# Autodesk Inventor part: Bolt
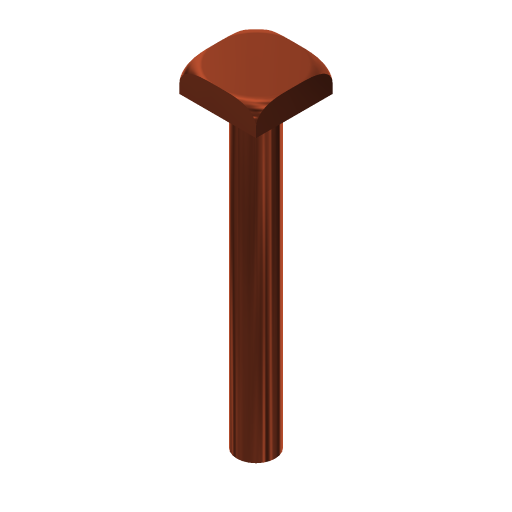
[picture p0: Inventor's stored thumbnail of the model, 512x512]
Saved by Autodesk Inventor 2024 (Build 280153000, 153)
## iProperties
Created: 2009-04
Part Number: Bolt
Document SubType Name: Modeling
Designer: Sham
Density: 8.92 g/cm^3
Material: Copper, Alloy
Appearance: Copper - Satin
Author: Sham
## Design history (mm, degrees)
sketch "Sketch1"
  geometry: L1 (-12, 12)-(12, 12); L2 (12, 12)-(12, -12); L3 (12, -12)-(-12, -12); L4 (-12, -12)-(-12, 12); 1 further point
  constraints: 8 end point, 2 parallel, 2 perpendicular, 1 horizontal, 1 other
  dimensions: "d0" = 24 distance of L1.start L1.end; "d1" = 12 distance from line of L2 point (0, 0); "d2" = 12 distance from line of L1 point (0, 0)
extrude "Extrusion1" new body sketch "Sketch1" distance "d3" = 8; taper "d4" = 0 deg
sketch "Sketch2"
  geometry: C1 r 6 at (0, 0)
  constraints: 1 centre point
  dimensions: "d5" = 12 diameter of C1
extrude "Extrusion2" join sketch "Sketch2" distance "d6" = 96; taper "d7" = 0 deg
workpoint "Work Point1"
workplane "Work Plane1"
sketch "Sketch3"
  geometry: L1 (33.941, 5)-(33.941, 6); L2 (28.941, 0)-(28.405, 0); L3 (16.971, 125.007)-(16.971, -22.043) reference; A1 r 5 centre (28.941, 5) between (28.941, 0) and (33.941, 5); 1 further point
  constraints: 4 end point, 2 point on circle, 2 point on line, 2 tangent, 1 centre point, 1 perpendicular
  dimensions: "d10" = 5 radius of A1
revolve "Revolution1" sketch "Sketch3" stored, may be unused: angle "d12" = 90 deg
body "Solid1"
other parameters: "d11" = 90 deg
